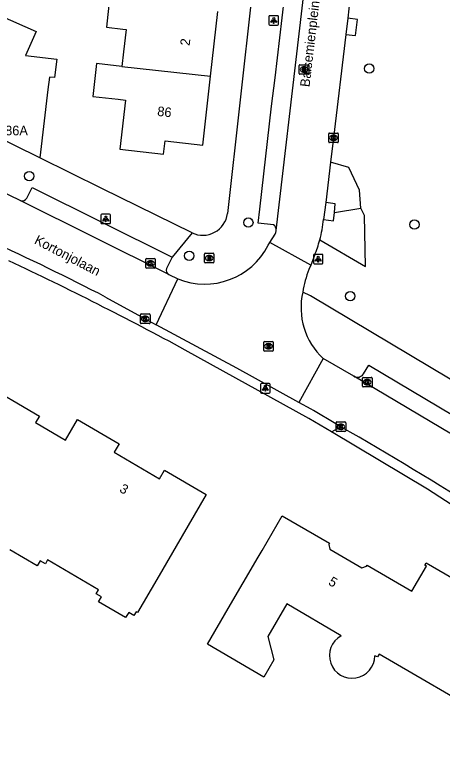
# Model space of a CAD drawing. Extents: x 161696 to 162377, y 380761 to 381673.
# Drawn here: x 161827.5 to 161872.3, y 381017.3 to 381093.8 of the extents above; entities that cross this region are included whole.
import ezdxf

# ---------------------------------------------------------------- set-up
doc = ezdxf.new("R2010")
doc.units = 0
for name, color, linetype in [('IMGEO_Boom', 7, 'Continuous'), ('IMGEO_Brandkraan', 7, 'Continuous'), ('IMGEO_Groenvoorziening', 7, 'Continuous'), ('IMGEO_Kolk', 7, 'Continuous'), ('IMGEO_Lichtpunt', 7, 'Continuous'), ('IMGEO_Muur', 7, 'Continuous'), ('IMGEO_Openbare_ruimte_label', 7, 'Continuous'), ('IMGEO_Pand', 7, 'Continuous'), ('IMGEO_Pand_nummerreeks', 7, 'Continuous'), ('IMGEO_Rijbaan_lokaal_open', 7, 'Continuous'), ('IMGEO_Rioolput', 7, 'Continuous'), ('IMGEO_Voetpad_open', 7, 'Continuous')]:
    doc.layers.add(name, color=color, linetype=linetype)

msp = doc.modelspace()

# ---------------------------------------------------------------- linework, layer by layer
at = {"layer": 'IMGEO_Boom'}
for centre in [(161864.643, 381088.119), (161829.076, 381076.878), (161851.995, 381072.016), (161869.375, 381071.814), (161845.805, 381068.556), (161862.65, 381064.325)]:
    msp.add_circle(centre, 0.489, dxfattribs=at)
at = {"layer": 'IMGEO_Brandkraan'}
for p, q in [((161847.399, 381067.882), (161847.399, 381068.734)), ((161847.474, 381068.808), (161848.326, 381068.808)), ((161847.887, 381068.588), (161847.912, 381068.588)), ((161848.4, 381068.734), (161848.4, 381067.882)), ((161848.326, 381067.808), (161847.474, 381067.808)), ((161847.91, 381068.028), (161847.885, 381068.028))]:
    msp.add_line(p, q, dxfattribs=at)
for points in [[(161847.399, 381067.882), (161847.399, 381068.734)], [(161847.474, 381068.808), (161848.326, 381068.808)], [(161847.747, 381068.508), (161847.747, 381068.108), (161847.96, 381068.108)], [(161847.978, 381068.508), (161847.747, 381068.508)], [(161847.926, 381068.427), (161847.872, 381068.427), (161847.872, 381068.351)], [(161847.872, 381068.351), (161847.925, 381068.351)], [(161848.4, 381068.734), (161848.4, 381067.882)], [(161848.326, 381067.808), (161847.474, 381067.808)], [(161847.934, 381068.275), (161847.872, 381068.275), (161847.872, 381068.194)], [(161847.872, 381068.194), (161847.934, 381068.194)]]:
    msp.add_lwpolyline(points, dxfattribs=at)
for centre, radius, start, end in [((161847.476, 381068.732), 0.0765, 91.55205, 178.44795), ((161847.476, 381068.732), 0.0765, 91.55205, 178.44795), ((161847.927, 381068.389), 0.0379, 267.82845, 90.93552), ((161847.982, 381068.363), 0.145, 59.4692, 91.53667), ((161848.007, 381068.41), 0.0922, 285.51372, 58.15012), ((161848.324, 381068.732), 0.0765, 1.55205, 88.44795), ((161848.324, 381068.732), 0.0765, 1.55205, 88.44795), ((161847.476, 381067.884), 0.0765, 181.55205, 268.44795), ((161847.476, 381067.884), 0.0765, 181.55205, 268.44795), ((161847.935, 381068.234), 0.0404, 269.87594, 90.50774), ((161847.966, 381068.359), 0.251, 268.66757, 293.53466), ((161848.012, 381068.218), 0.105, 301.31148, 78.98903), ((161848.324, 381067.884), 0.0765, 271.55205, 358.44795), ((161848.324, 381067.884), 0.0765, 271.55205, 358.44795)]:
    msp.add_arc(centre, radius, start, end, dxfattribs=at)
for centre, major_axis, ratio, start_param, end_param in [((161847.886, 381068.308), (-0.387, 0.002), 0.722429, 4.712389, 7.853982), ((161847.911, 381068.308), (-0.39, 0.002), 0.717154, 1.570796, 4.712389)]:
    msp.add_ellipse(centre, major_axis=major_axis, ratio=ratio, start_param=start_param, end_param=end_param, dxfattribs=at)
at = {"layer": 'IMGEO_Groenvoorziening'}
for points in [[(161863.759, 381073.519), (161863.62, 381075.409), (161862.509, 381077.782), (161860.594, 381078.32)], [(161859.466, 381070.205), (161864.237, 381067.43), (161864.131, 381072.768), (161863.759, 381073.519)], [(161861, 381073.076), (161863.759, 381073.519)]]:
    msp.add_lwpolyline(points, dxfattribs=at)
at = {"layer": 'IMGEO_Kolk'}
for p, q in [((161860.474, 381081.376), (161861.326, 381081.376)), ((161860.399, 381080.45), (161860.399, 381081.302)), ((161860.91, 381080.596), (161860.885, 381080.596)), ((161860.887, 381081.156), (161860.912, 381081.156)), ((161861.4, 381081.302), (161861.4, 381080.45)), ((161861.326, 381080.376), (161860.474, 381080.376)), ((161841.261, 381067.328), (161841.261, 381068.18)), ((161841.336, 381068.254), (161842.188, 381068.254)), ((161841.749, 381068.034), (161841.774, 381068.034)), ((161842.262, 381068.18), (161842.262, 381067.328)), ((161842.188, 381067.254), (161841.336, 381067.254)), ((161841.772, 381067.474), (161841.747, 381067.474)), ((161840.706, 381061.537), (161840.706, 381062.389)), ((161840.781, 381062.463), (161841.633, 381062.463)), ((161841.194, 381062.243), (161841.219, 381062.243)), ((161841.707, 381062.389), (161841.707, 381061.537)), ((161841.633, 381061.463), (161840.781, 381061.463)), ((161841.217, 381061.683), (161841.192, 381061.683)), ((161863.933, 381054.91), (161863.933, 381055.762)), ((161864.008, 381055.836), (161864.86, 381055.836)), ((161864.421, 381055.616), (161864.446, 381055.616)), ((161864.934, 381055.762), (161864.934, 381054.91)), ((161864.86, 381054.836), (161864.008, 381054.836)), ((161864.444, 381055.056), (161864.419, 381055.056)), ((161861.175, 381050.246), (161861.175, 381051.098)), ((161861.25, 381051.172), (161862.102, 381051.172)), ((161861.663, 381050.952), (161861.688, 381050.952)), ((161862.176, 381051.098), (161862.176, 381050.246)), ((161862.102, 381050.172), (161861.25, 381050.172)), ((161861.686, 381050.392), (161861.661, 381050.392))]:
    msp.add_line(p, q, dxfattribs=at)
for points in [[(161860.474, 381081.376), (161861.326, 381081.376)], [(161860.399, 381080.45), (161860.399, 381081.302)], [(161860.72, 381081.076), (161860.843, 381081.076), (161860.843, 381080.925), (161860.973, 381081.076), (161861.137, 381081.076), (161860.991, 381080.925), (161861.144, 381080.676), (161860.992, 381080.676), (161860.907, 381080.84), (161860.843, 381080.773), (161860.843, 381080.676), (161860.72, 381080.676), (161860.72, 381081.076)], [(161861.4, 381081.302), (161861.4, 381080.45)], [(161861.326, 381080.376), (161860.474, 381080.376)], [(161841.261, 381067.328), (161841.261, 381068.18)], [(161841.336, 381068.254), (161842.188, 381068.254)], [(161841.582, 381067.954), (161841.705, 381067.954), (161841.705, 381067.803), (161841.835, 381067.954), (161841.999, 381067.954), (161841.853, 381067.803), (161842.006, 381067.554), (161841.854, 381067.554), (161841.769, 381067.718), (161841.705, 381067.651), (161841.705, 381067.554), (161841.582, 381067.554), (161841.582, 381067.954)], [(161842.262, 381068.18), (161842.262, 381067.328)], [(161842.188, 381067.254), (161841.336, 381067.254)], [(161840.706, 381061.537), (161840.706, 381062.389)], [(161840.781, 381062.463), (161841.633, 381062.463)], [(161841.707, 381062.389), (161841.707, 381061.537)], [(161841.633, 381061.463), (161840.781, 381061.463)], [(161841.027, 381062.163), (161841.15, 381062.163), (161841.15, 381062.012), (161841.28, 381062.163), (161841.444, 381062.163), (161841.298, 381062.012), (161841.451, 381061.763), (161841.299, 381061.763), (161841.214, 381061.927), (161841.15, 381061.86), (161841.15, 381061.763), (161841.027, 381061.763), (161841.027, 381062.163)], [(161863.933, 381054.91), (161863.933, 381055.762)], [(161864.008, 381055.836), (161864.86, 381055.836)], [(161864.254, 381055.536), (161864.377, 381055.536), (161864.377, 381055.385), (161864.507, 381055.536), (161864.671, 381055.536), (161864.525, 381055.385), (161864.678, 381055.136), (161864.526, 381055.136), (161864.441, 381055.3), (161864.377, 381055.233), (161864.377, 381055.136), (161864.254, 381055.136), (161864.254, 381055.536)], [(161864.934, 381055.762), (161864.934, 381054.91)], [(161864.86, 381054.836), (161864.008, 381054.836)], [(161861.175, 381050.246), (161861.175, 381051.098)], [(161861.25, 381051.172), (161862.102, 381051.172)], [(161861.496, 381050.872), (161861.619, 381050.872), (161861.619, 381050.721), (161861.749, 381050.872), (161861.913, 381050.872), (161861.767, 381050.721), (161861.92, 381050.472), (161861.768, 381050.472), (161861.683, 381050.636), (161861.619, 381050.569), (161861.619, 381050.472), (161861.496, 381050.472), (161861.496, 381050.872)], [(161862.176, 381051.098), (161862.176, 381050.246)], [(161862.102, 381050.172), (161861.25, 381050.172)]]:
    msp.add_lwpolyline(points, dxfattribs=at)
for centre, start, end in [((161860.476, 381081.3), 91.55205, 178.44795), ((161860.476, 381081.3), 91.55205, 178.44795), ((161861.324, 381081.3), 1.55205, 88.44795), ((161861.324, 381081.3), 1.55205, 88.44795), ((161860.476, 381080.452), 181.55205, 268.44795), ((161860.476, 381080.452), 181.55205, 268.44795), ((161861.324, 381080.452), 271.55205, 358.44795), ((161861.324, 381080.452), 271.55205, 358.44795), ((161841.338, 381068.178), 91.55205, 178.44795), ((161841.338, 381068.178), 91.55205, 178.44795), ((161842.186, 381068.178), 1.55205, 88.44795), ((161842.186, 381068.178), 1.55205, 88.44795), ((161841.338, 381067.33), 181.55205, 268.44795), ((161841.338, 381067.33), 181.55205, 268.44795), ((161842.186, 381067.33), 271.55205, 358.44795), ((161842.186, 381067.33), 271.55205, 358.44795), ((161840.783, 381062.387), 91.55205, 178.44795), ((161840.783, 381062.387), 91.55205, 178.44795), ((161841.631, 381062.387), 1.55205, 88.44795), ((161841.631, 381062.387), 1.55205, 88.44795), ((161840.783, 381061.539), 181.55205, 268.44795), ((161840.783, 381061.539), 181.55205, 268.44795), ((161841.631, 381061.539), 271.55205, 358.44795), ((161841.631, 381061.539), 271.55205, 358.44795), ((161864.01, 381055.76), 91.55205, 178.44795), ((161864.01, 381055.76), 91.55205, 178.44795), ((161864.858, 381055.76), 1.55205, 88.44795), ((161864.858, 381055.76), 1.55205, 88.44795), ((161864.01, 381054.912), 181.55205, 268.44795), ((161864.01, 381054.912), 181.55205, 268.44795), ((161864.858, 381054.912), 271.55205, 358.44795), ((161864.858, 381054.912), 271.55205, 358.44795), ((161861.252, 381051.096), 91.55205, 178.44795), ((161861.252, 381051.096), 91.55205, 178.44795), ((161862.1, 381051.096), 1.55205, 88.44795), ((161862.1, 381051.096), 1.55205, 88.44795), ((161861.252, 381050.248), 181.55205, 268.44795), ((161861.252, 381050.248), 181.55205, 268.44795), ((161862.1, 381050.248), 271.55205, 358.44795), ((161862.1, 381050.248), 271.55205, 358.44795)]:
    msp.add_arc(centre, 0.0765, start, end, dxfattribs=at)
for centre, major_axis, ratio, start_param, end_param in [((161860.886, 381080.876), (-0.387, 0.002), 0.722429, 4.712389, 7.853982), ((161860.911, 381080.876), (-0.39, 0.002), 0.717154, 1.570796, 4.712389), ((161841.748, 381067.754), (-0.387, 0.002), 0.722429, 4.712389, 7.853982), ((161841.773, 381067.754), (-0.39, 0.002), 0.717154, 1.570796, 4.712389), ((161841.193, 381061.963), (-0.387, 0.002), 0.722429, 4.712389, 7.853982), ((161841.218, 381061.963), (-0.39, 0.002), 0.717154, 1.570796, 4.712389), ((161864.42, 381055.336), (-0.387, 0.002), 0.722429, 4.712389, 7.853982), ((161864.445, 381055.336), (-0.39, 0.002), 0.717154, 1.570796, 4.712389), ((161861.662, 381050.672), (-0.387, 0.002), 0.722429, 4.712389, 7.853982), ((161861.687, 381050.672), (-0.39, 0.002), 0.717154, 1.570796, 4.712389)]:
    msp.add_ellipse(centre, major_axis=major_axis, ratio=ratio, start_param=start_param, end_param=end_param, dxfattribs=at)
at = {"layer": 'IMGEO_Lichtpunt'}
for p, q in [((161855.057, 381093.652), (161854.249, 381093.652)), ((161855.057, 381093.652), (161854.249, 381093.652)), ((161854.155, 381093.557), (161854.155, 381092.75)), ((161854.155, 381093.557), (161854.155, 381092.75)), ((161855.151, 381092.75), (161855.151, 381093.557)), ((161855.151, 381092.75), (161855.151, 381093.557)), ((161854.249, 381092.656), (161855.057, 381092.656)), ((161854.249, 381092.656), (161855.057, 381092.656)), ((161836.576, 381072.808), (161836.576, 381072.001)), ((161836.576, 381072.808), (161836.576, 381072.001)), ((161837.478, 381072.903), (161836.67, 381072.903)), ((161837.478, 381072.903), (161836.67, 381072.903)), ((161837.572, 381072.001), (161837.572, 381072.808)), ((161837.572, 381072.001), (161837.572, 381072.808)), ((161836.67, 381071.907), (161837.478, 381071.907)), ((161836.67, 381071.907), (161837.478, 381071.907)), ((161858.803, 381068.603), (161858.803, 381067.796)), ((161858.803, 381068.603), (161858.803, 381067.796)), ((161859.705, 381068.698), (161858.897, 381068.698)), ((161859.705, 381068.698), (161858.897, 381068.698)), ((161859.799, 381067.796), (161859.799, 381068.603)), ((161859.799, 381067.796), (161859.799, 381068.603)), ((161858.897, 381067.702), (161859.705, 381067.702)), ((161858.897, 381067.702), (161859.705, 381067.702)), ((161853.272, 381055.1), (161853.272, 381054.293)), ((161853.272, 381055.1), (161853.272, 381054.293)), ((161854.174, 381055.195), (161853.366, 381055.195)), ((161854.174, 381055.195), (161853.366, 381055.195)), ((161854.268, 381054.293), (161854.268, 381055.1)), ((161854.268, 381054.293), (161854.268, 381055.1)), ((161853.366, 381054.199), (161854.174, 381054.199)), ((161853.366, 381054.199), (161854.174, 381054.199))]:
    msp.add_line(p, q, dxfattribs=at)
for points in [[(161854.529, 381093.221), (161854.568, 381093.193), (161854.38, 381092.931), (161854.342, 381092.958), (161854.529, 381093.221)], [(161854.631, 381093.173), (161854.678, 381093.173), (161854.678, 381092.851), (161854.631, 381092.851), (161854.631, 381093.173)], [(161854.741, 381093.193), (161854.779, 381093.22), (161854.966, 381092.958), (161854.927, 381092.93), (161854.741, 381093.193)], [(161836.95, 381072.472), (161836.989, 381072.444), (161836.801, 381072.182), (161836.763, 381072.209), (161836.95, 381072.472)], [(161837.052, 381072.424), (161837.099, 381072.424), (161837.099, 381072.102), (161837.052, 381072.102), (161837.052, 381072.424)], [(161837.162, 381072.444), (161837.2, 381072.471), (161837.387, 381072.209), (161837.348, 381072.181), (161837.162, 381072.444)], [(161859.177, 381068.267), (161859.216, 381068.239), (161859.028, 381067.977), (161858.99, 381068.004), (161859.177, 381068.267)], [(161859.279, 381068.219), (161859.326, 381068.219), (161859.326, 381067.897), (161859.279, 381067.897), (161859.279, 381068.219)], [(161859.389, 381068.239), (161859.427, 381068.266), (161859.614, 381068.004), (161859.575, 381067.976), (161859.389, 381068.239)], [(161853.646, 381054.764), (161853.685, 381054.736), (161853.497, 381054.474), (161853.459, 381054.501), (161853.646, 381054.764)], [(161853.748, 381054.716), (161853.795, 381054.716), (161853.795, 381054.394), (161853.748, 381054.394), (161853.748, 381054.716)], [(161853.858, 381054.736), (161853.896, 381054.763), (161854.083, 381054.501), (161854.044, 381054.473), (161853.858, 381054.736)]]:
    msp.add_lwpolyline(points, dxfattribs=at)
for centre in [(161854.654, 381093.355), (161837.075, 381072.606), (161859.302, 381068.401), (161853.771, 381054.898)]:
    msp.add_circle(centre, 0.0994, dxfattribs=at)
for centre, start, end in [((161854.249, 381093.557), 90, 180), ((161854.249, 381093.557), 90, 180), ((161855.057, 381093.557), 0, 90), ((161855.057, 381093.557), 0, 90), ((161854.249, 381092.75), 180, 270), ((161854.249, 381092.75), 180, 270), ((161855.057, 381092.75), 270, 0), ((161855.057, 381092.75), 270, 360), ((161836.67, 381072.808), 90, 180), ((161836.67, 381072.808), 90, 180), ((161837.478, 381072.808), 0, 90), ((161837.478, 381072.808), 0, 90), ((161836.67, 381072.001), 180, 270), ((161836.67, 381072.001), 180, 270), ((161837.478, 381072.001), 270, 0), ((161837.478, 381072.001), 270, 360), ((161858.897, 381068.603), 90, 180), ((161858.897, 381068.603), 90, 180), ((161859.705, 381068.603), 0, 90), ((161859.705, 381068.603), 0, 90), ((161858.897, 381067.796), 180, 270), ((161858.897, 381067.796), 180, 270), ((161859.705, 381067.796), 270, 0), ((161859.705, 381067.796), 270, 360), ((161853.366, 381055.1), 90, 180), ((161853.366, 381055.1), 90, 180), ((161854.174, 381055.1), 0, 90), ((161854.174, 381055.1), 0, 90), ((161853.366, 381054.293), 180, 270), ((161853.366, 381054.293), 180, 270), ((161854.174, 381054.293), 270, 0), ((161854.174, 381054.293), 270, 360)]:
    msp.add_arc(centre, 0.0946, start, end, dxfattribs=at)
at = {"layer": 'IMGEO_Muur'}
msp.add_lwpolyline([(161836.651, 381075.598), (161830.182, 381078.784)], dxfattribs=at)
at = {"layer": 'IMGEO_Pand'}
for points in [[(161837.48, 381095.449), (161837.14, 381092.444), (161838.863, 381092.249), (161839.205, 381092.21), (161838.943, 381089.876), (161838.772, 381088.354)], [(161825.878, 381093.711), (161829.793, 381092.008), (161828.689, 381089.472), (161831.945, 381089.09), (161831.72, 381087.171), (161831.175, 381087.235), (161831.021, 381085.925), (161830.182, 381078.784)], [(161848.031, 381087.318), (161848.793, 381094.1)], [(161838.772, 381088.354), (161836.126, 381088.65), (161835.74, 381085.203), (161838.384, 381084.907), (161839.135, 381084.823), (161838.557, 381079.682), (161843.135, 381079.167), (161843.291, 381080.552), (161847.22, 381080.11), (161848.031, 381087.318)], [(161838.772, 381088.354), (161848.031, 381087.318)], [(161830.182, 381078.784), (161824.784, 381081.427)], [(161823.955, 381055.411), (161830.134, 381051.769), (161829.741, 381051.102), (161832.867, 381049.267), (161834.13, 381051.421), (161838.464, 381048.899), (161837.945, 381048.009), (161842.706, 381045.222), (161843.225, 381046.15), (161847.594, 381043.596), (161845.077, 381039.275), (161842.416, 381034.706), (161840.402, 381031.248), (161840.249, 381031.335), (161840.025, 381030.947), (161839.478, 381031.263), (161839.16, 381030.716), (161836.32, 381032.355)], [(161847.709, 381027.924), (161849.885, 381031.659), (161853.025, 381037.05), (161853.428, 381037.742), (161855.541, 381041.371), (161860.479, 381038.496), (161860.408, 381038.367), (161860.532, 381037.877), (161863.858, 381035.911), (161864.371, 381036.084), (161864.419, 381036.194), (161869.101, 381033.478), (161870.622, 381036.09), (161870.45, 381036.191), (161870.606, 381036.459), (161883.104, 381029.186)], [(161836.32, 381032.355), (161836.637, 381032.902), (161836.089, 381033.218), (161836.33, 381033.627), (161831, 381036.741), (161830.759, 381036.337), (161830.213, 381036.662), (161829.887, 381036.116), (161827.056, 381037.804)], [(161861.69, 381028.822), (161856.012, 381032.153), (161854.045, 381028.75), (161854.674, 381026.286), (161853.628, 381024.476), (161847.709, 381027.924)], [(161877.421, 381020.057), (161865.674, 381026.895), (161865.507, 381026.607), (161865.224, 381026.733)]]:
    msp.add_lwpolyline(points, dxfattribs=at)
msp.add_arc((161862.849, 381026.749), 2.375, 119.20101, 359.62306, dxfattribs=at)
at = {"layer": 'IMGEO_Rijbaan_lokaal_open'}
for points in [[(161854.916, 381071.199), (161859.721, 381112.337), (161859.924, 381113.838)], [(161854.613, 381071.79), (161853.008, 381071.962), (161853.184, 381073.43), (161854.427, 381084.19), (161854.783, 381087.167), (161856.019, 381097.655), (161856.269, 381100.034), (161857.835, 381113.32), (161859.155, 381113.233)], [(161863.772, 381105.601), (161863.248, 381101.216), (161862.407, 381093.385)], [(161862.407, 381093.385), (161862.202, 381091.684)], [(161862.202, 381091.684), (161860.9, 381080.876), (161860.594, 381078.32)], [(161860.594, 381078.32), (161860.092, 381074.125)], [(161828.135, 381074.321), (161823.972, 381076.331)], [(161843.678, 381066.577), (161828.135, 381074.321)], [(161860.092, 381074.125), (161859.856, 381072.357)], [(161854.243, 381069.925), (161854.8, 381070.818)], [(161854.905, 381071.121), (161854.916, 381071.199)], [(161854.065, 381069.641), (161854.243, 381069.925)], [(161858.526, 381067.562), (161854.243, 381069.925)], [(161858.92, 381068.59), (161858.526, 381067.562)], [(161858.526, 381067.562), (161858.337, 381067.124)], [(161842.339, 381061.338), (161844.624, 381066.127)], [(161843.678, 381066.577), (161844.624, 381066.127)], [(161837.066, 381064.238), (161841.207, 381061.963), (161842.339, 381061.338)], [(161857.272, 381053.223), (161850.791, 381056.809), (161842.339, 381061.338)], [(161859.824, 381057.819), (161857.272, 381053.223)], [(161863.015, 381055.945), (161859.824, 381057.819)], [(161874.352, 381049.226), (161863.015, 381055.945)], [(161861.681, 381050.67), (161861.155, 381050.983), (161858.808, 381052.367), (161858.559, 381052.511), (161857.272, 381053.223)]]:
    msp.add_lwpolyline(points, dxfattribs=at)
for centre, radius, start, end in [((161846.702, 381073.629), 13.215, 344.98134, 354.47457), ((161854.288, 381071.25), 0.63, 355.35207, 58.93548), ((161853.32, 381071.501), 1.63, 335.24192, 346.53214), ((161698.387, 380794.47), 303.326, 62.79372, 65.34151), ((161846.624, 381073.647), 13.295, 337.64472, 344.99649), ((161847.42, 381073.055), 7.471, 248.02245, 332.80873), ((161867.71, 381063.306), 10.121, 157.83623, 171.78438), ((161864.685, 381063.107), 7.183, 166.7623, 227.40947), ((161652.747, 380687.297), 419.158, 57.70406, 60.10176)]:
    msp.add_arc(centre, radius, start, end, dxfattribs=at)
at = {"layer": 'IMGEO_Rioolput'}
for p, q in [((161857.321, 381087.602), (161857.321, 381088.454)), ((161857.396, 381088.528), (161858.248, 381088.528)), ((161857.809, 381088.308), (161857.834, 381088.308)), ((161858.322, 381088.454), (161858.322, 381087.602)), ((161858.248, 381087.528), (161857.396, 381087.528)), ((161857.832, 381087.748), (161857.807, 381087.748)), ((161853.601, 381058.662), (161853.601, 381059.514)), ((161853.676, 381059.588), (161854.528, 381059.588)), ((161854.089, 381059.368), (161854.114, 381059.368)), ((161854.602, 381059.514), (161854.602, 381058.662)), ((161854.528, 381058.588), (161853.676, 381058.588)), ((161854.112, 381058.808), (161854.087, 381058.808))]:
    msp.add_line(p, q, dxfattribs=at)
for points in [[(161857.321, 381087.602), (161857.321, 381088.454)], [(161857.396, 381088.528), (161858.248, 381088.528)], [(161857.91, 381088.226), (161857.658, 381088.228), (161857.658, 381087.828)], [(161858.322, 381088.454), (161858.322, 381087.602)], [(161858.248, 381087.528), (161857.396, 381087.528)], [(161857.658, 381087.828), (161857.782, 381087.828), (161857.782, 381087.99), (161857.793, 381087.99)], [(161857.836, 381088.147), (161857.782, 381088.147), (161857.782, 381088.066)], [(161857.782, 381088.066), (161857.834, 381088.066)], [(161857.84, 381087.961), (161857.911, 381087.828), (161858.051, 381087.828), (161857.986, 381087.954)], [(161853.601, 381058.662), (161853.601, 381059.514)], [(161853.676, 381059.588), (161854.528, 381059.588)], [(161854.19, 381059.286), (161853.938, 381059.288), (161853.938, 381058.888)], [(161854.116, 381059.207), (161854.062, 381059.207), (161854.062, 381059.126)], [(161854.602, 381059.514), (161854.602, 381058.662)], [(161854.528, 381058.588), (161853.676, 381058.588)], [(161853.938, 381058.888), (161854.062, 381058.888), (161854.062, 381059.05), (161854.073, 381059.05)], [(161854.062, 381059.126), (161854.114, 381059.126)], [(161854.12, 381059.021), (161854.191, 381058.888), (161854.331, 381058.888), (161854.266, 381059.014)]]:
    msp.add_lwpolyline(points, dxfattribs=at)
for centre, radius, start, end in [((161857.398, 381088.452), 0.0765, 91.55205, 178.44795), ((161857.398, 381088.452), 0.0765, 91.55205, 178.44795), ((161857.909, 381088.116), 0.109, 350.36119, 89.41601), ((161858.246, 381088.452), 0.0765, 1.55205, 88.44795), ((161858.246, 381088.452), 0.0765, 1.55205, 88.44795), ((161857.398, 381087.604), 0.0765, 181.55205, 268.44795), ((161857.398, 381087.604), 0.0765, 181.55205, 268.44795), ((161857.792, 381087.937), 0.0533, 26.02933, 88.69889), ((161857.818, 381088.255), 0.19, 274.7715, 282.96867), ((161857.842, 381088.051), 0.0964, 77.00612, 93.18647), ((161857.856, 381088.108), 0.0378, 276.66336, 79.67722), ((161857.907, 381088.116), 0.112, 277.58423, 350.98172), ((161857.891, 381087.901), 0.108, 29.51342, 73.79051), ((161858.246, 381087.604), 0.0765, 271.55205, 358.44795), ((161858.246, 381087.604), 0.0765, 271.55205, 358.44795), ((161853.678, 381059.512), 0.0765, 91.55205, 178.44795), ((161853.678, 381059.512), 0.0765, 91.55205, 178.44795), ((161854.122, 381059.111), 0.0964, 77.00612, 93.18647), ((161854.136, 381059.168), 0.0378, 276.66336, 79.67722), ((161854.189, 381059.176), 0.109, 350.36119, 89.41601), ((161854.187, 381059.176), 0.112, 277.58423, 350.98172), ((161854.526, 381059.512), 0.0765, 1.55205, 88.44795), ((161854.526, 381059.512), 0.0765, 1.55205, 88.44795), ((161853.678, 381058.664), 0.0765, 181.55205, 268.44795), ((161853.678, 381058.664), 0.0765, 181.55205, 268.44795), ((161854.072, 381058.997), 0.0533, 26.02933, 88.69889), ((161854.098, 381059.315), 0.19, 274.7715, 282.96867), ((161854.171, 381058.961), 0.108, 29.51342, 73.79051), ((161854.526, 381058.664), 0.0765, 271.55205, 358.44795), ((161854.526, 381058.664), 0.0765, 271.55205, 358.44795)]:
    msp.add_arc(centre, radius, start, end, dxfattribs=at)
for centre, major_axis, ratio, start_param, end_param in [((161857.808, 381088.028), (-0.387, 0.002), 0.722429, 4.712389, 7.853982), ((161857.833, 381088.028), (-0.39, 0.002), 0.717154, 1.570796, 4.712389), ((161854.088, 381059.088), (-0.387, 0.002), 0.722429, 4.712389, 7.853982), ((161854.113, 381059.088), (-0.39, 0.002), 0.717154, 1.570796, 4.712389)]:
    msp.add_ellipse(centre, major_axis=major_axis, ratio=ratio, start_param=start_param, end_param=end_param, dxfattribs=at)
at = {"layer": 'IMGEO_Voetpad_open'}
for points in [[(161833.302, 381175.355), (161852.88, 381124.681), (161854.96, 381119.298), (161849.813, 381072.956)], [(161862.202, 381091.684), (161863.195, 381091.592), (161863.41, 381093.267), (161862.407, 381093.385)], [(161846.103, 381070.942), (161836.651, 381075.598), (161830.182, 381078.784)], [(161828.827, 381074.573), (161829.389, 381075.701), (161844.019, 381068.403)], [(161861, 381073.076), (161861.093, 381073.97), (161860.092, 381074.125)], [(161859.856, 381072.357), (161860.91, 381072.211), (161861, 381073.076)], [(161846.103, 381070.942), (161844.019, 381068.403)], [(161844.019, 381068.403), (161843.446, 381067.215)], [(161883.582, 381049.424), (161858.502, 381064.372), (161857.693, 381064.752)], [(161860.683, 381050.137), (161858.317, 381051.533), (161845.401, 381058.686)], [(161864.034, 381056.191), (161864.59, 381057.114), (161874.843, 381050.997), (161874.18, 381049.856)], [(161860.683, 381050.137), (161861.681, 381050.67)], [(161909.012, 381017.255), (161901.853, 381023.073), (161892.907, 381029.507), (161882.643, 381036.459), (161870.723, 381044.134), (161860.683, 381050.137)]]:
    msp.add_lwpolyline(points, dxfattribs=at)
for centre, radius, start, end in [((161828.334, 381074.85), 0.565, 249.37027, 330.64912), ((161847.225, 381073.3), 2.611, 244.56242, 352.42885), ((161675.26, 380745.042), 356.82, 61.52176, 64.84256), ((161843.901, 381067.019), 0.495, 156.72427, 243.24194), ((161863.392, 381056.617), 0.77, 240.69844, 326.44609)]:
    msp.add_arc(centre, radius, start, end, dxfattribs=at)

# ---------------------------------------------------------------- texts
at = {"layer": 'IMGEO_Openbare_ruimte_label'}
for s, rotation, p in [('Balsemienplein', 83.28012, (161858.388, 381086.152)), ('Kortonjolaan', 332.40963, (161829.524, 381069.881))]:
    msp.add_text(s, height=1, rotation=rotation, dxfattribs=at).set_placement(p)
at = {"layer": 'IMGEO_Pand_nummerreeks'}
for s, rotation, p in [('2', 83.58434, (161845.849, 381090.469)), ('86', 353.58139, (161842.427, 381083.185)), ('3', 329.65616, (161838.431, 381043.924)), ('5', 329.41265, (161860.289, 381034.211))]:
    msp.add_text(s, height=1, rotation=rotation, dxfattribs=at).set_placement(p)
msp.add_text('86A', height=1, dxfattribs=at).set_placement((161826.551, 381081.146))

doc.saveas('drawing.dxf')
